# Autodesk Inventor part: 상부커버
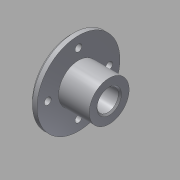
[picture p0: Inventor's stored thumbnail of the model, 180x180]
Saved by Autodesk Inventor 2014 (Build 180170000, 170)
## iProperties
Created: 2015-09
Part Number: 상부커버
Material: 알루미늄 6061
Document SubType Name: Modeling
Designer: mduedu
Density: 1 g/cm^3
Appearance: Aluminum - Flat
Author: mduedu
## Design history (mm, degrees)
sketch "스케치1"
  geometry: L1 (-12.5, 0)-(12.5, 0); L2 (-12.5, 0)-(-12.5, 27); L3 (-12.5, 27)-(-7.5, 27); L4 (-7.5, 27)-(-7.5, 13); L5 (-7.5, 13)-(12.5, 13); L6 (12.5, 13)-(12.5, 0); 2 further points
  constraints: 12 end point, 2 parallel, 2 perpendicular, 1 coincident, 1 horizontal, 1 midpoint, 1 vertical
  dimensions: "d0" = 25 distance of L1.start L1.end; "d2" = 5 distance of L2.end L3.end; "d3" = 26 diameter of L5 L1; "d4" = 54 diameter of L3 L1
revolve "회전1" sketch "스케치1" stored, may be unused: angle "d5" = 90 deg
hole "구멍1" diameter "d8" = 14; stored, may be unused: countersink angle "d12" = 90 deg, drill point angle "d14" = 118 deg; dims "d6" = 10, "d7" = 10, "d9" = 6, "d10" = 4, "d11" = 2, "d13" = 8
chamfer "모따기1" distance "d15" = 1; stored, may be unused: second distance "d16" = 2, angle "d17" = 45 deg
chamfer "모따기2" distance "d18" = 2; stored, may be unused: second distance "d19" = 2, angle "d20" = 45 deg
sketch "스케치2" dims "d21" = 40
  geometry: 6 further points
  constraints: 2 vertical alignment, 1 coincident, 7 other
  dimensions: "d25" = 360 deg dimension on point (0, 0) point (0, 20) (derived)
sketch "스케치3"
  geometry: 4 further points
hole "구멍2" sketch "스케치3" at (0, 20), (-20, 0), (20, 0), (0, -20) diameter "d27" = 4.5; stored, may be unused: countersink angle "d31" = 90 deg, drill point angle "d33" = 0 deg; dims "d28" = 6, "d29" = 4, "d30" = 2, "d32" = 8
node "솔리드1"
